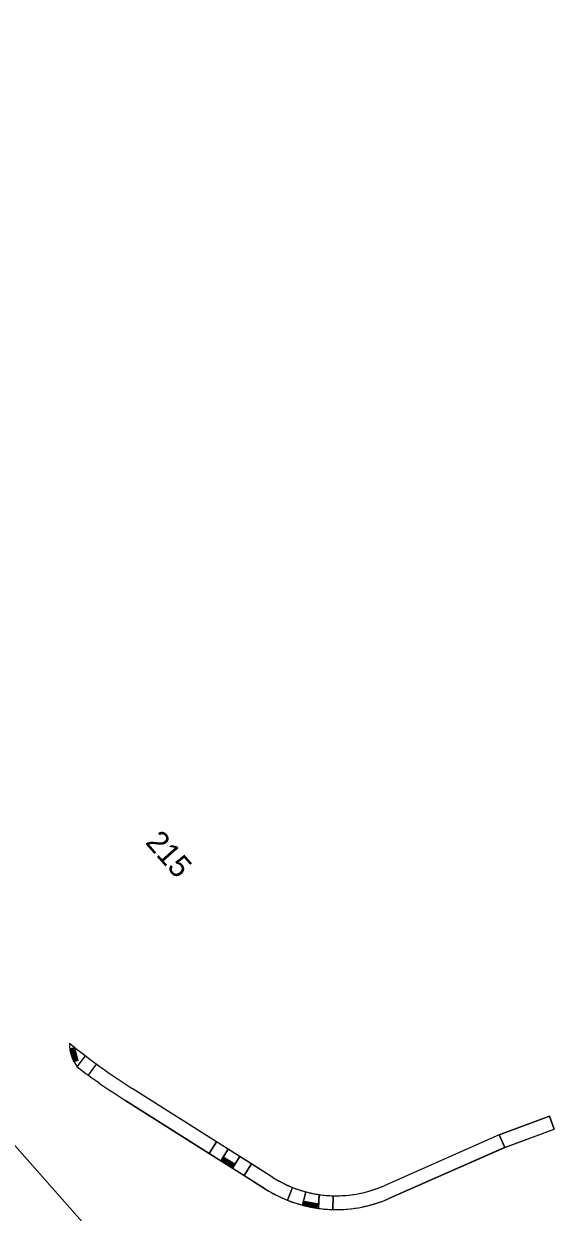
# Model space of a CAD drawing. Extents: x -5665 to 1997148, y 4 to 827579.
# Drawn here: x 1970532.4 to 1970724.9, y 803626.5 to 804057.8 of the extents above; entities that cross this region are included whole.
import ezdxf

# ---------------------------------------------------------------- set-up
doc = ezdxf.new("R2010")
doc.units = 0
for name, color, linetype in [('RD_HC_CL_Rel', 7, 'Continuous'), ('RD_HC_TX_Rel_Sta50', 7, 'Continuous'), ('RD_PD_SW', 7, 'Continuous')]:
    doc.layers.add(name, color=color, linetype=linetype)

msp = doc.modelspace()

# ---------------------------------------------------------------- linework, layer by layer
at = {"layer": 'RD_HC_CL_Rel'}
msp.add_line((1970169.33, 804057.78), (1970562.8, 803612.71), dxfattribs=at)
at = {"layer": 'RD_PD_SW'}
for p, q in [((1970551.82, 803679.24), (1970554.86, 803683.22)), ((1970555.91, 803676.19), (1970558.87, 803680.22)), ((1970622.8, 803639.13), (1970571.81, 803671.41)), ((1970602.35, 803652.07), (1970571.81, 803671.41)), ((1970620.13, 803634.9), (1970569.13, 803667.18)), ((1970569.13, 803667.18), (1970599.68, 803647.85)), ((1970704.98, 803654.59), (1970723.17, 803661.36)), ((1970723.17, 803661.36), (1970704.98, 803654.59)), ((1970723.17, 803661.36), (1970724.91, 803656.68)), ((1970724.91, 803656.68), (1970723.17, 803661.36)), ((1970704.98, 803654.59), (1970663.17, 803636.13)), ((1970704.98, 803654.59), (1970663.17, 803636.13)), ((1970707, 803650.02), (1970704.98, 803654.59)), ((1970704.98, 803654.59), (1970707, 803650.02)), ((1970706.86, 803649.96), (1970724.91, 803656.68)), ((1970707, 803650.01), (1970724.91, 803656.68)), ((1970602.35, 803652.07), (1970599.68, 803647.85)), ((1970599.68, 803647.85), (1970602.35, 803652.07)), ((1970599.68, 803647.85), (1970602.35, 803652.07)), ((1970606.58, 803649.4), (1970602.35, 803652.07)), ((1970603.91, 803645.17), (1970606.58, 803649.4)), ((1970606.58, 803649.4), (1970603.91, 803645.17)), ((1970603.91, 803645.17), (1970606.58, 803649.4)), ((1970610.8, 803646.72), (1970606.58, 803649.4)), ((1970665.19, 803631.55), (1970707, 803650.02)), ((1970706.86, 803649.96), (1970665.19, 803631.55)), ((1970599.68, 803647.85), (1970603.91, 803645.17)), ((1970603.91, 803645.17), (1970608.13, 803642.5)), ((1970610.8, 803646.72), (1970608.13, 803642.5)), ((1970608.13, 803642.5), (1970610.8, 803646.72)), ((1970608.13, 803642.5), (1970610.8, 803646.72)), ((1970615.03, 803644.05), (1970610.8, 803646.72)), ((1970608.13, 803642.5), (1970612.35, 803639.82)), ((1970612.35, 803639.82), (1970615.03, 803644.05)), ((1970615.03, 803644.05), (1970612.35, 803639.82)), ((1970612.35, 803639.82), (1970615.03, 803644.05)), ((1970622.8, 803639.13), (1970615.03, 803644.05)), ((1970612.35, 803639.82), (1970620.13, 803634.9)), ((1970628.16, 803630.82), (1970630, 803635.47)), ((1970630, 803635.47), (1970628.16, 803630.82)), ((1970628.16, 803630.82), (1970630, 803635.47)), ((1970633.52, 803629.06), (1970634.8, 803633.89)), ((1970634.8, 803633.89), (1970633.52, 803629.06)), ((1970634.8, 803633.89), (1970633.52, 803629.06)), ((1970639.39, 803627.89), (1970639.65, 803632.9)), ((1970639.65, 803632.9), (1970639.39, 803627.89)), ((1970639.65, 803632.9), (1970639.39, 803627.89)), ((1970644.61, 803627.48), (1970644.73, 803632.47)), ((1970644.73, 803632.47), (1970644.61, 803627.48)), ((1970644.61, 803627.48), (1970644.73, 803632.47))]:
    msp.add_line(p, q, dxfattribs=at)
for points in [[(1970550.83, 803686.33), (1970552.09, 803681.51), (1970550.55, 803681.11), (1970549.29, 803685.93)], [(1970609.02, 803643.89), (1970604.8, 803646.53), (1970603.95, 803645.18), (1970608.18, 803642.53)], [(1970639.12, 803629.55), (1970634.22, 803630.45), (1970633.93, 803628.88), (1970638.83, 803627.98)]]:
    msp.add_lwpolyline(points, close=True, dxfattribs=at)
msp.add_lwpolyline([(1970707, 803650.02), (1970707, 803650.01)], dxfattribs=at)
for centre, radius in [((1970549.64, 803685.73), 0.146), ((1970549.64, 803685.73), 0.073), ((1970549.74, 803685.34), 0.146), ((1970549.74, 803685.34), 0.073), ((1970549.84, 803684.96), 0.146), ((1970549.84, 803684.96), 0.073), ((1970549.95, 803684.57), 0.146), ((1970549.95, 803684.57), 0.073), ((1970550.05, 803684.18), 0.146), ((1970550.05, 803684.18), 0.073), ((1970550.13, 803685.86), 0.146), ((1970550.15, 803683.8), 0.146), ((1970550.13, 803685.86), 0.073), ((1970550.23, 803685.47), 0.146), ((1970550.15, 803683.8), 0.073), ((1970550.25, 803683.41), 0.146), ((1970550.23, 803685.47), 0.073), ((1970550.33, 803685.08), 0.146), ((1970550.33, 803685.08), 0.073), ((1970550.43, 803684.7), 0.146), ((1970550.43, 803684.7), 0.073), ((1970550.53, 803684.31), 0.146), ((1970550.53, 803684.31), 0.073), ((1970550.62, 803685.99), 0.146), ((1970550.63, 803683.92), 0.146), ((1970550.62, 803685.99), 0.073), ((1970550.63, 803683.92), 0.073), ((1970550.72, 803685.6), 0.146), ((1970550.73, 803683.54), 0.146), ((1970550.72, 803685.6), 0.073), ((1970550.73, 803683.54), 0.073), ((1970550.82, 803685.21), 0.146), ((1970550.82, 803685.21), 0.073), ((1970550.92, 803684.83), 0.146), ((1970550.92, 803684.83), 0.073), ((1970551.02, 803684.44), 0.146), ((1970551.02, 803684.44), 0.073), ((1970551.12, 803684.05), 0.146), ((1970551.12, 803684.05), 0.073), ((1970551.22, 803683.66), 0.146), ((1970551.22, 803683.66), 0.073), ((1970550.25, 803683.41), 0.073), ((1970550.35, 803683.02), 0.146), ((1970550.35, 803683.02), 0.073), ((1970550.45, 803682.64), 0.146), ((1970550.45, 803682.64), 0.073), ((1970550.55, 803682.25), 0.146), ((1970550.55, 803682.25), 0.073), ((1970550.65, 803681.86), 0.146), ((1970550.65, 803681.86), 0.073), ((1970550.76, 803681.47), 0.146), ((1970550.76, 803681.47), 0.073), ((1970550.83, 803683.15), 0.146), ((1970550.83, 803683.15), 0.073), ((1970550.93, 803682.76), 0.146), ((1970550.93, 803682.76), 0.073), ((1970551.04, 803682.37), 0.146), ((1970551.04, 803682.37), 0.073), ((1970551.14, 803681.99), 0.146), ((1970551.14, 803681.99), 0.073), ((1970551.24, 803681.6), 0.146), ((1970551.24, 803681.6), 0.073), ((1970551.33, 803683.28), 0.146), ((1970551.33, 803683.28), 0.073), ((1970551.43, 803682.89), 0.146), ((1970551.43, 803682.89), 0.073), ((1970551.53, 803682.5), 0.146), ((1970551.53, 803682.5), 0.073), ((1970551.63, 803682.12), 0.146), ((1970551.63, 803682.12), 0.073), ((1970551.73, 803681.73), 0.146), ((1970551.73, 803681.73), 0.073), ((1970604.36, 803645.27), 0.146), ((1970604.36, 803645.27), 0.073), ((1970604.63, 803645.69), 0.146), ((1970604.63, 803645.69), 0.073), ((1970604.7, 803645.05), 0.146), ((1970604.7, 803645.05), 0.073), ((1970604.9, 803646.12), 0.146), ((1970604.9, 803646.12), 0.073), ((1970604.97, 803645.48), 0.146), ((1970604.97, 803645.48), 0.073), ((1970605.04, 803644.84), 0.146), ((1970605.04, 803644.84), 0.073), ((1970605.24, 803645.91), 0.146), ((1970605.24, 803645.91), 0.073), ((1970605.3, 803645.26), 0.146), ((1970605.3, 803645.26), 0.073), ((1970605.38, 803644.63), 0.146), ((1970605.57, 803645.7), 0.146), ((1970605.57, 803645.7), 0.073), ((1970605.64, 803645.05), 0.146), ((1970605.64, 803645.05), 0.073), ((1970605.91, 803645.48), 0.146), ((1970605.91, 803645.48), 0.073), ((1970605.98, 803644.84), 0.146), ((1970605.98, 803644.84), 0.073), ((1970606.25, 803645.27), 0.146), ((1970606.25, 803645.27), 0.073), ((1970606.32, 803644.63), 0.146), ((1970606.59, 803645.06), 0.146), ((1970606.59, 803645.06), 0.073), ((1970606.93, 803644.85), 0.146), ((1970606.93, 803644.85), 0.073), ((1970607.27, 803644.64), 0.146), ((1970605.38, 803644.63), 0.073), ((1970605.72, 803644.42), 0.146), ((1970605.72, 803644.42), 0.073), ((1970606.06, 803644.21), 0.146), ((1970606.06, 803644.21), 0.073), ((1970606.32, 803644.63), 0.073), ((1970606.4, 803643.99), 0.146), ((1970606.4, 803643.99), 0.073), ((1970606.66, 803644.42), 0.146), ((1970606.66, 803644.42), 0.073), ((1970606.74, 803643.78), 0.146), ((1970606.74, 803643.78), 0.073), ((1970607, 803644.2), 0.146), ((1970607, 803644.2), 0.073), ((1970607.08, 803643.57), 0.146), ((1970607.08, 803643.57), 0.073), ((1970607.34, 803643.99), 0.146), ((1970607.27, 803644.64), 0.073), ((1970607.34, 803643.99), 0.073), ((1970607.42, 803643.36), 0.146), ((1970607.42, 803643.36), 0.073), ((1970607.61, 803644.42), 0.146), ((1970607.68, 803643.78), 0.146), ((1970607.61, 803644.42), 0.073), ((1970607.68, 803643.78), 0.073), ((1970607.75, 803643.15), 0.146), ((1970607.75, 803643.15), 0.073), ((1970607.95, 803644.21), 0.146), ((1970608.02, 803643.57), 0.146), ((1970607.95, 803644.21), 0.073), ((1970608.02, 803643.57), 0.073), ((1970608.09, 803642.93), 0.146), ((1970608.09, 803642.93), 0.073), ((1970608.29, 803644), 0.146), ((1970608.36, 803643.36), 0.146), ((1970608.29, 803644), 0.073), ((1970608.36, 803643.36), 0.073), ((1970608.63, 803643.79), 0.146), ((1970608.63, 803643.79), 0.073), ((1970634.28, 803629.11), 0.146), ((1970634.28, 803629.11), 0.073), ((1970634.37, 803629.6), 0.146), ((1970634.37, 803629.6), 0.073), ((1970634.46, 803630.11), 0.146), ((1970634.46, 803630.11), 0.073), ((1970634.68, 803629.04), 0.146), ((1970634.68, 803629.04), 0.073), ((1970634.77, 803629.53), 0.146), ((1970634.77, 803629.53), 0.073), ((1970634.86, 803630.03), 0.146), ((1970634.86, 803630.03), 0.073), ((1970635.07, 803628.97), 0.146), ((1970635.07, 803628.97), 0.073), ((1970635.16, 803629.46), 0.146), ((1970635.16, 803629.46), 0.073), ((1970635.25, 803629.96), 0.146), ((1970635.25, 803629.96), 0.073), ((1970635.46, 803628.9), 0.146), ((1970635.46, 803628.9), 0.073), ((1970635.55, 803629.39), 0.146), ((1970635.55, 803629.39), 0.073), ((1970635.64, 803629.89), 0.146), ((1970635.64, 803629.89), 0.073), ((1970635.86, 803628.83), 0.146), ((1970635.86, 803628.83), 0.073), ((1970635.95, 803629.32), 0.146), ((1970635.95, 803629.32), 0.073), ((1970636.04, 803629.82), 0.146), ((1970636.04, 803629.82), 0.073), ((1970636.25, 803628.75), 0.146), ((1970636.25, 803628.75), 0.073), ((1970636.34, 803629.24), 0.146), ((1970636.34, 803629.24), 0.073), ((1970636.43, 803629.74), 0.146), ((1970636.43, 803629.74), 0.073), ((1970636.64, 803628.68), 0.146), ((1970636.64, 803628.68), 0.073), ((1970636.73, 803629.17), 0.146), ((1970636.73, 803629.17), 0.073), ((1970636.82, 803629.67), 0.146), ((1970636.82, 803629.67), 0.073), ((1970637.04, 803628.61), 0.146), ((1970637.04, 803628.61), 0.073), ((1970637.13, 803629.1), 0.146), ((1970637.13, 803629.1), 0.073), ((1970637.22, 803629.6), 0.146), ((1970637.22, 803629.6), 0.073), ((1970637.43, 803628.54), 0.146), ((1970637.43, 803628.54), 0.073), ((1970637.52, 803629.03), 0.146), ((1970637.52, 803629.03), 0.073), ((1970637.61, 803629.53), 0.146), ((1970637.61, 803629.53), 0.073), ((1970637.82, 803628.46), 0.146), ((1970637.82, 803628.46), 0.073), ((1970637.91, 803628.96), 0.146), ((1970637.91, 803628.96), 0.073), ((1970638.01, 803629.46), 0.146), ((1970638.01, 803629.46), 0.073), ((1970638.22, 803628.39), 0.146), ((1970638.22, 803628.39), 0.073), ((1970638.31, 803628.88), 0.146), ((1970638.31, 803628.88), 0.073), ((1970638.4, 803629.38), 0.146), ((1970638.4, 803629.38), 0.073), ((1970638.61, 803628.32), 0.146), ((1970638.61, 803628.32), 0.073), ((1970638.7, 803628.81), 0.146), ((1970638.7, 803628.81), 0.073), ((1970638.79, 803629.31), 0.146), ((1970638.79, 803629.31), 0.073)]:
    msp.add_circle(centre, radius, dxfattribs=at)
for centre, radius, start, end in [((1970696.42, 803868.28), 233, 230.766, 237.667), ((1970696.42, 803868.28), 233, 230.766, 237.667), ((1970562.55, 803687.44), 13.5, 178.4561, 217.388), ((1970696.42, 803868.28), 238, 232.5862, 237.667), ((1970696.42, 803868.28), 238, 232.5862, 237.667), ((1970645.8, 803675.46), 43, 237.667, 248.4381), ((1970645.8, 803675.46), 43, 237.667, 293.832), ((1970645.8, 803675.46), 43, 268.5748, 293.832), ((1970645.8, 803675.46), 48, 237.667, 248.4381), ((1970645.8, 803675.46), 48, 237.667, 293.832), ((1970645.8, 803675.46), 43, 248.4381, 255.1774), ((1970645.8, 803675.46), 43, 255.1774, 261.7745), ((1970645.8, 803675.46), 43, 261.7745, 268.5748), ((1970645.8, 803675.46), 48, 248.4381, 255.1774), ((1970645.8, 803675.46), 48, 255.1774, 262.3247), ((1970645.8, 803675.46), 48, 262.3247, 268.5748), ((1970645.8, 803675.46), 48, 268.5748, 293.832)]:
    msp.add_arc(centre, radius, start, end, dxfattribs=at)

# ---------------------------------------------------------------- texts
at = {"layer": 'RD_HC_TX_Rel_Sta50'}
msp.add_text('215', height=8, rotation=311.479, dxfattribs=at).set_placement((1970576.26, 803760.54))

doc.saveas('drawing.dxf')
